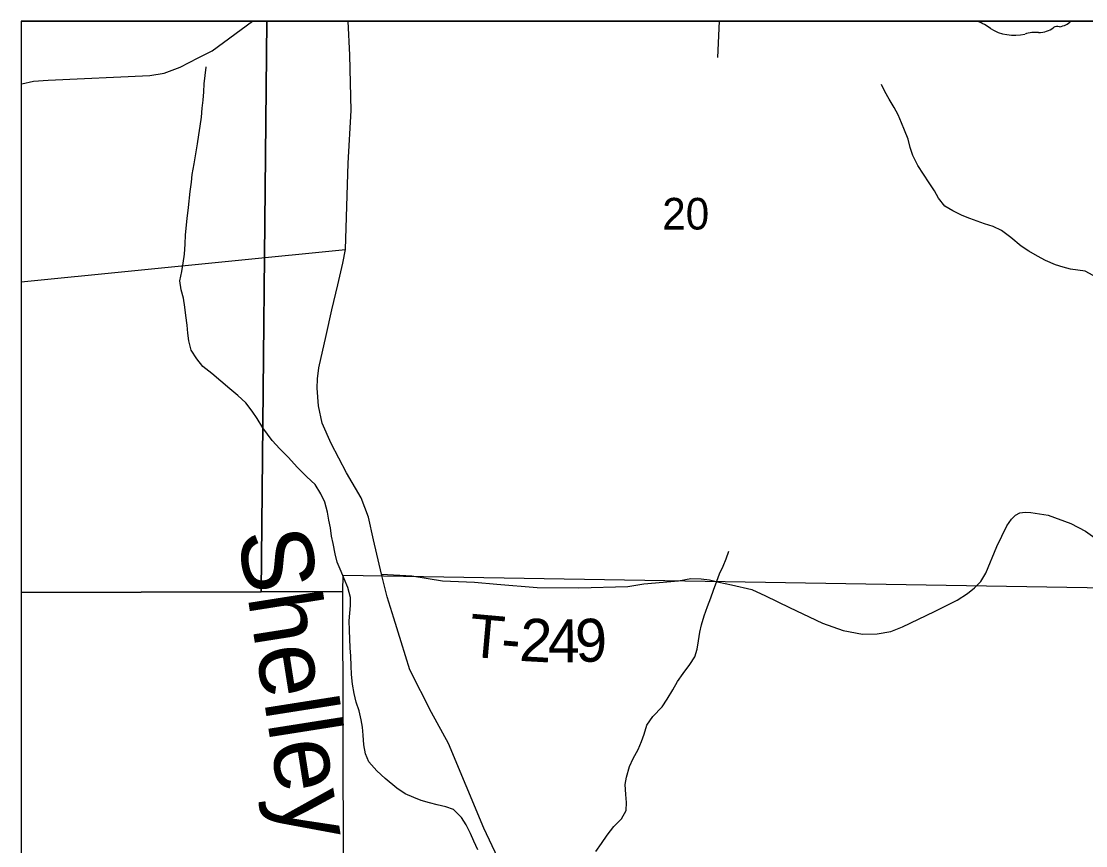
# Model space of a CAD drawing. Extents: x 2.1 to 8.9, y 14.1 to 20.9.
# Drawn here: x 2.1 to 3.51, y 19.809 to 20.9 of the extents above; entities that cross this region are included whole.
import ezdxf

# ---------------------------------------------------------------- set-up
doc = ezdxf.new("R2010")
doc.units = 0
for name, color, linetype in [('Default', 7, 'Continuous'), ('GM_X_City_Street', 7, 'Continuous'), ('GM_X_County_Road', 7, 'Continuous'), ('GM_X_County_Road_Text', 7, 'Continuous'), ('GM_X_Interchange_Ramps', 7, 'Continuous'), ('GM_X_Minor_River_Text', 7, 'Continuous'), ('GM_X_Rail_Line_Text', 7, 'Continuous'), ('PV_P_Text', 7, 'Continuous'), ('SH_Cut_Line', 7, 'Continuous'), ('SH_Data', 7, 'Continuous'), ('TX_P_Misc', 7, 'Continuous')]:
    doc.layers.add(name, color=color, linetype=linetype)

msp = doc.modelspace()

# ---------------------------------------------------------------- linework, layer by layer
at = {"layer": 'Default'}
for p, q in [((2.4251, 20.9), (2.1, 20.9)), ((2.1, 20.9), (2.1, 20.144)), ((7.8225, 20.9), (2.1, 20.9)), ((2.1, 20.9), (2.1, 19.1502)), ((2.4251, 20.9), (2.4179, 20.145)), ((2.4179, 20.145), (2.4251, 20.9)), ((3.5394, 20.9), (2.4251, 20.9)), ((2.526, 20.1453), (2.5263, 20.1669)), ((2.5263, 20.1669), (3.5383, 20.1501)), ((2.1, 20.144), (2.4179, 20.145)), ((2.4179, 20.145), (2.1, 20.144)), ((2.4179, 20.145), (2.526, 20.1453)), ((2.526, 20.1453), (2.4179, 20.145)), ((2.5274, 19.148), (2.526, 20.1453)), ((2.1, 20.144), (2.1, 19.1493))]:
    msp.add_line(p, q, dxfattribs=at)
at = {"layer": 'GM_X_City_Street'}
for p, q in [((2.535, 20.8553), (2.5329, 20.9)), ((3.0226, 20.8522), (3.0248, 20.9)), ((2.5369, 20.7821), (2.535, 20.8553)), ((2.5329, 20.7122), (2.5369, 20.7821)), ((2.5292, 20.5978), (2.5329, 20.7122)), ((2.1, 20.5554), (2.5292, 20.5978)), ((2.5259, 20.5799), (2.5292, 20.5978)), ((2.5191, 20.551), (2.5259, 20.5799)), ((2.5112, 20.5182), (2.5191, 20.551)), ((2.5038, 20.484), (2.5112, 20.5182)), ((2.4942, 20.4413), (2.5038, 20.484)), ((2.4922, 20.4268), (2.4942, 20.4413)), ((2.4919, 20.4144), (2.4922, 20.4268)), ((2.4936, 20.391), (2.4919, 20.4144)), ((2.4986, 20.3681), (2.4936, 20.391)), ((2.5104, 20.3412), (2.4986, 20.3681)), ((2.5309, 20.3025), (2.5104, 20.3412)), ((2.5501, 20.2692), (2.5309, 20.3025)), ((2.5597, 20.2438), (2.5501, 20.2692)), ((2.5663, 20.2136), (2.5597, 20.2438)), ((3.4112, 20.2409), (3.4168, 20.2462)), ((3.4168, 20.2462), (3.4226, 20.2493)), ((3.4226, 20.2493), (3.4295, 20.2505)), ((3.4295, 20.2505), (3.4371, 20.2498)), ((3.4371, 20.2498), (3.4599, 20.2462)), ((3.4599, 20.2462), (3.4899, 20.2355)), ((3.3919, 20.205), (3.4054, 20.2322)), ((3.4054, 20.2322), (3.4112, 20.2409)), ((3.4899, 20.2355), (3.5094, 20.2253)), ((3.5094, 20.2253), (3.528, 20.212)), ((2.577, 20.1683), (2.5663, 20.2136)), ((3.3772, 20.1698), (3.3919, 20.205)), ((2.5845, 20.1383), (2.577, 20.1683)), ((2.577, 20.1683), (2.6174, 20.166)), ((2.6174, 20.166), (2.6578, 20.1594)), ((2.6578, 20.1594), (2.7003, 20.1579)), ((2.9243, 20.1554), (2.9705, 20.1594)), ((2.9705, 20.1594), (2.9865, 20.1626)), ((2.9865, 20.1626), (3.0004, 20.1622)), ((3.0004, 20.1622), (3.0116, 20.1606)), ((3.0116, 20.1606), (3.0239, 20.1579)), ((3.3625, 20.1502), (3.3706, 20.1587)), ((3.3706, 20.1587), (3.3772, 20.1698)), ((2.7003, 20.1579), (2.73, 20.1551)), ((2.73, 20.1551), (2.7832, 20.1505)), ((2.7832, 20.1505), (2.8382, 20.1503)), ((2.8382, 20.1503), (2.9032, 20.1521)), ((2.9032, 20.1521), (2.9243, 20.1554)), ((3.0239, 20.1579), (3.0406, 20.1541)), ((3.0406, 20.1541), (3.0673, 20.148)), ((3.0673, 20.148), (3.0857, 20.1394)), ((3.3529, 20.1427), (3.3625, 20.1502)), ((2.5936, 20.1102), (2.5845, 20.1383)), ((3.0857, 20.1394), (3.1176, 20.1241)), ((3.3094, 20.1187), (3.3395, 20.134)), ((3.3395, 20.134), (3.3529, 20.1427)), ((3.1176, 20.1241), (3.1613, 20.1034)), ((3.267, 20.0985), (3.3094, 20.1187)), ((2.6031, 20.0786), (2.5936, 20.1102)), ((3.1613, 20.1034), (3.1884, 20.0939)), ((3.1884, 20.0939), (3.2141, 20.0889)), ((3.2141, 20.0889), (3.2334, 20.0891)), ((3.2334, 20.0891), (3.2517, 20.0926)), ((3.2517, 20.0926), (3.267, 20.0985)), ((2.6146, 20.0416), (2.6031, 20.0786)), ((2.6432, 19.9853), (2.6146, 20.0416)), ((2.6658, 19.9443), (2.6432, 19.9853)), ((2.7127, 19.8323), (2.6658, 19.9443)), ((2.7589, 19.7337), (2.7127, 19.8323))]:
    msp.add_line(p, q, dxfattribs=at)
at = {"layer": 'GM_X_County_Road'}
msp.add_line((3.4902, 20.9), (3.3669, 20.9), dxfattribs=at)
for centre, major_axis, start_param, end_param in [((3.3298, 20.8442), (0.079, 0), 0.823519, 1.081646), ((3.4478, 20.9066), (0.0267, 0), 4.691044, 5.507374), ((3.472, 20.8872), (0.00752, 0), 1.147584, 2.315152), ((3.4688, 20.9147), (0.0282, 0), 4.937069, 5.572482), ((3.4152, 20.9216), (0.0501, 0), 4.026481, 4.996735), ((3.4442, 20.8524), (0.0412, 0), 1.495662, 1.94098)]:
    msp.add_ellipse(centre, major_axis=major_axis, ratio=0.8, start_param=start_param, end_param=end_param, dxfattribs=at)
at = {"layer": 'GM_X_Interchange_Ramps'}
for p, q in [((2.526, 20.1453), (2.5263, 20.1669)), ((2.5263, 20.1669), (3.5383, 20.1501)), ((2.5274, 19.148), (2.526, 20.1453))]:
    msp.add_line(p, q, dxfattribs=at)
at = {"layer": 'GM_X_Rail_Line_Text'}
for p, q in [((2.353, 20.8608), (2.4062, 20.9)), ((2.3106, 20.8394), (2.3344, 20.8515)), ((2.3344, 20.8515), (2.353, 20.8608)), ((2.2894, 20.8315), (2.3106, 20.8394)), ((2.1163, 20.8207), (2.1356, 20.8223)), ((2.1356, 20.8223), (2.2704, 20.8281)), ((2.2704, 20.8281), (2.2894, 20.8315)), ((2.1, 20.8168), (2.1009, 20.8171)), ((2.1009, 20.8171), (2.1163, 20.8207))]:
    msp.add_line(p, q, dxfattribs=at)
at = {"layer": 'SH_Cut_Line'}
for p, q in [((7.8225, 20.9), (2.1, 20.9)), ((2.1, 20.9), (2.1, 14.1))]:
    msp.add_line(p, q, dxfattribs=at)
at = {"layer": 'SH_Data'}
for q in [(2.1, 14.1), (8.9, 20.9), (2.1, 14.1), (8.9, 20.9)]:
    msp.add_line((2.1, 20.9), q, dxfattribs=at)
at = {"layer": 'TX_P_Misc'}
for p, q in [((2.3437, 20.8282), (2.3449, 20.8393)), ((2.3449, 20.8393), (2.3449, 20.8396)), ((2.3422, 20.8171), (2.3437, 20.8282)), ((2.3409, 20.7958), (2.3417, 20.8068)), ((2.3417, 20.8068), (2.3422, 20.8171)), ((3.2436, 20.807), (3.2391, 20.8163)), ((3.2492, 20.7969), (3.2436, 20.807)), ((2.3394, 20.7851), (2.3409, 20.7958)), ((3.256, 20.7861), (3.2492, 20.7969)), ((2.3386, 20.7733), (2.3394, 20.7851)), ((3.2612, 20.7764), (3.256, 20.7861)), ((2.3371, 20.7611), (2.3386, 20.7733)), ((3.2658, 20.7658), (3.2612, 20.7764)), ((3.2699, 20.7561), (3.2658, 20.7658)), ((2.3352, 20.7496), (2.3371, 20.7611)), ((3.2744, 20.7441), (3.2699, 20.7561)), ((2.331, 20.7244), (2.3333, 20.7378)), ((2.3333, 20.7378), (2.3352, 20.7496)), ((3.2774, 20.7328), (3.2744, 20.7441)), ((2.3291, 20.7114), (2.331, 20.7244)), ((3.2808, 20.7226), (3.2774, 20.7328)), ((3.2873, 20.7091), (3.2808, 20.7226)), ((2.3265, 20.6972), (2.3291, 20.7114)), ((3.3025, 20.686), (3.2873, 20.7091)), ((2.3253, 20.6869), (2.3265, 20.6972)), ((2.3238, 20.6747), (2.3253, 20.6869)), ((3.3093, 20.6756), (3.3025, 20.686)), ((2.3215, 20.6534), (2.3238, 20.6747)), ((3.3145, 20.6659), (3.3093, 20.6756)), ((3.3232, 20.6555), (3.3145, 20.6659)), ((2.3196, 20.6392), (2.3215, 20.6534)), ((3.3337, 20.649), (3.3232, 20.6555)), ((2.3176, 20.6175), (2.3196, 20.6392)), ((3.346, 20.6429), (3.3337, 20.649)), ((3.3564, 20.639), (3.346, 20.6429)), ((3.3756, 20.632), (3.3564, 20.639)), ((3.3872, 20.6282), (3.3756, 20.632)), ((3.398, 20.6232), (3.3872, 20.6282)), ((2.3169, 20.6049), (2.3176, 20.6175)), ((3.4104, 20.6137), (3.398, 20.6232)), ((3.4241, 20.6024), (3.4104, 20.6137)), ((2.3162, 20.592), (2.3169, 20.6049)), ((3.4342, 20.5958), (3.4241, 20.6024)), ((3.4458, 20.5893), (3.4342, 20.5958)), ((2.3146, 20.5798), (2.3162, 20.592)), ((3.4566, 20.5836), (3.4458, 20.5893)), ((3.4697, 20.5779), (3.4566, 20.5836)), ((2.31, 20.5564), (2.3127, 20.569)), ((2.3127, 20.569), (2.3146, 20.5798)), ((3.4797, 20.5748), (3.4697, 20.5779)), ((3.4897, 20.5721), (3.4797, 20.5748)), ((3.4992, 20.5705), (3.4897, 20.5721)), ((3.5088, 20.5693), (3.4992, 20.5705)), ((3.5196, 20.5635), (3.5088, 20.5693)), ((2.3119, 20.5447), (2.31, 20.5564)), ((2.315, 20.5334), (2.3119, 20.5447)), ((2.3165, 20.5216), (2.315, 20.5334)), ((2.3179, 20.5107), (2.3165, 20.5216)), ((2.3195, 20.4978), (2.3179, 20.5107)), ((2.3206, 20.4872), (2.3195, 20.4978)), ((2.322, 20.4773), (2.3206, 20.4872)), ((2.3251, 20.4649), (2.322, 20.4773)), ((2.3323, 20.4533), (2.3251, 20.4649)), ((2.3406, 20.4433), (2.3323, 20.4533)), ((2.3523, 20.4338), (2.3406, 20.4433)), ((2.3644, 20.4235), (2.3523, 20.4338)), ((2.3761, 20.4136), (2.3644, 20.4235)), ((2.387, 20.4048), (2.3761, 20.4136)), ((2.3972, 20.3949), (2.387, 20.4048)), ((2.4059, 20.3841), (2.3972, 20.3949)), ((2.4123, 20.3745), (2.4059, 20.3841)), ((2.4199, 20.3621), (2.4123, 20.3745)), ((2.4322, 20.3454), (2.4199, 20.3621)), ((2.4425, 20.334), (2.4322, 20.3454)), ((2.4539, 20.3225), (2.4425, 20.334)), ((2.4653, 20.31), (2.4539, 20.3225)), ((2.4782, 20.2971), (2.4653, 20.31)), ((2.4892, 20.2868), (2.4782, 20.2971)), ((2.4968, 20.2744), (2.4892, 20.2868)), ((2.5021, 20.2636), (2.4968, 20.2744)), ((2.5056, 20.2504), (2.5021, 20.2636)), ((2.5074, 20.2398), (2.5056, 20.2504)), ((2.5093, 20.2296), (2.5074, 20.2398)), ((2.5107, 20.2186), (2.5093, 20.2296)), ((2.513, 20.2088), (2.5107, 20.2186)), ((2.5157, 20.1952), (2.513, 20.2088)), ((2.5183, 20.1842), (2.5157, 20.1952)), ((3.0294, 20.179), (3.0333, 20.1886)), ((3.0333, 20.1886), (3.0372, 20.1986)), ((2.5236, 20.1719), (2.5183, 20.1842)), ((3.0248, 20.1689), (3.0294, 20.179)), ((2.5277, 20.1621), (2.5236, 20.1719)), ((2.5323, 20.1505), (2.5277, 20.1621)), ((3.0167, 20.147), (3.0213, 20.1589)), ((3.0213, 20.1589), (3.0248, 20.1689)), ((2.5361, 20.1373), (2.5323, 20.1505)), ((3.0133, 20.137), (3.0167, 20.147)), ((2.536, 20.127), (2.5361, 20.1373)), ((3.0087, 20.1255), (3.0133, 20.137)), ((2.5344, 20.1064), (2.536, 20.127)), ((3.0045, 20.1132), (3.0087, 20.1255)), ((2.5348, 20.0943), (2.5344, 20.1064)), ((3.0007, 20.1013), (3.0045, 20.1132)), ((2.5355, 20.0707), (2.5348, 20.0943)), ((2.9968, 20.0799), (2.9987, 20.0917)), ((2.9987, 20.0917), (3.0007, 20.1013)), ((2.9949, 20.0691), (2.9968, 20.0799)), ((2.5363, 20.0597), (2.5355, 20.0707)), ((2.537, 20.0468), (2.5363, 20.0597)), ((2.9921, 20.0588), (2.9949, 20.0691)), ((2.5374, 20.0354), (2.537, 20.0468)), ((2.9765, 20.0366), (2.9852, 20.0487)), ((2.9852, 20.0487), (2.9921, 20.0588)), ((2.5386, 20.0225), (2.5374, 20.0354)), ((2.9692, 20.0261), (2.9765, 20.0366)), ((2.5408, 20.0104), (2.5386, 20.0225)), ((2.9627, 20.0153), (2.9692, 20.0261)), ((2.5435, 19.9987), (2.5408, 20.0104)), ((2.9555, 20.0029), (2.9627, 20.0153)), ((2.5473, 19.9874), (2.5435, 19.9987)), ((2.9364, 19.9799), (2.9486, 19.9928)), ((2.9486, 19.9928), (2.9555, 20.0029)), ((2.5499, 19.9757), (2.5473, 19.9874)), ((2.5517, 19.9659), (2.5499, 19.9757)), ((2.9284, 19.9686), (2.9364, 19.9799)), ((2.5528, 19.9553), (2.5517, 19.9659)), ((2.925, 19.9567), (2.9284, 19.9686)), ((2.5536, 19.9424), (2.5528, 19.9553)), ((2.9215, 19.9467), (2.925, 19.9567)), ((2.5559, 19.9303), (2.5536, 19.9424)), ((2.9104, 19.9243), (2.9169, 19.9363)), ((2.9169, 19.9363), (2.9215, 19.9467)), ((2.5604, 19.9198), (2.5559, 19.9303)), ((2.571, 19.9079), (2.5604, 19.9198)), ((2.9054, 19.9135), (2.9104, 19.9243)), ((2.582, 19.898), (2.571, 19.9079)), ((2.9013, 19.8997), (2.9054, 19.9135)), ((2.5972, 19.8852), (2.582, 19.898)), ((2.8997, 19.8897), (2.9013, 19.8997)), ((2.6085, 19.8776), (2.5972, 19.8852)), ((2.6197, 19.8726), (2.6085, 19.8776)), ((2.9005, 19.8768), (2.8997, 19.8897)), ((2.9016, 19.8662), (2.9005, 19.8768)), ((2.6297, 19.8687), (2.6197, 19.8726)), ((2.6408, 19.8657), (2.6297, 19.8687)), ((2.6508, 19.8629), (2.6408, 19.8657)), ((2.6623, 19.8602), (2.6508, 19.8629)), ((2.9012, 19.8556), (2.9016, 19.8662)), ((2.6723, 19.8568), (2.6623, 19.8602)), ((2.6829, 19.8464), (2.6723, 19.8568)), ((2.8947, 19.8443), (2.9012, 19.8556)), ((2.6892, 19.8364), (2.6829, 19.8464)), ((2.6949, 19.8251), (2.6892, 19.8364)), ((2.876, 19.8228), (2.8847, 19.8341)), ((2.8847, 19.8341), (2.8947, 19.8443)), ((2.6994, 19.815), (2.6949, 19.8251)), ((2.8683, 19.8116), (2.876, 19.8228)), ((2.7047, 19.8034), (2.6994, 19.815)), ((2.8611, 19.8011), (2.8683, 19.8116))]:
    msp.add_line(p, q, dxfattribs=at)

# ---------------------------------------------------------------- texts
at = {"layer": 'GM_X_County_Road_Text'}
msp.add_text('20', height=0.04186, rotation=0, dxfattribs=at).set_placement((2.9488, 20.6244))
at = {"layer": 'GM_X_Minor_River_Text'}
for s, rotation, p in [('T', 354.9018, (2.6912, 20.0594)), ('2', 356.8414, (2.7589, 20.0536)), ('4', 0.1037, (2.7974, 20.0516)), ('9', 2.066, (2.8345, 20.0517)), ('-', 355.3014, (2.734, 20.0556))]:
    msp.add_text(s, height=0.0568, rotation=rotation, dxfattribs=at).set_placement(p)
at = {"layer": 'PV_P_Text'}
msp.add_text('Shelley', height=0.09467, rotation=278.9717, dxfattribs=at).set_placement((2.3864, 20.2224))

doc.saveas('drawing.dxf')
